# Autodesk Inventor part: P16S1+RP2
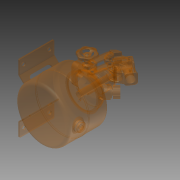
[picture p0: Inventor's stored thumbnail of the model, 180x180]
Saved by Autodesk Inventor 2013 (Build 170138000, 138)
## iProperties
Created: 2015-07
Part Number: P16S1+RP2
Material: Générique
Document SubType Name: Modeling
Designer: OL
Density: 1 g/cm^3
Author: OL
Norme de conversion: STEP AP203
Nom du fichier: P16S1+RP2.STEP
Préprocesseur: SolidWorks 2007
Postprocesseur: Build: 138, Release: 2013 RTM - Date: Thu 03/01/2012
Unités envoyées: millimètre
Incertitude: 1e-05
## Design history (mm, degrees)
node "P16S1+RP21"
feature "Composite1"
body "Srf1"
